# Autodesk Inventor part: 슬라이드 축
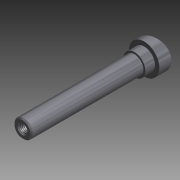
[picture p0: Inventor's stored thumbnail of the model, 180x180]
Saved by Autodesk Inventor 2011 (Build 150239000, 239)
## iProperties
Created: 2012-05
Part Number: 슬라이드 축
Document SubType Name: 모델링
Designer: SeoGD™
Mass: 169.555 g
Surface Area: 67.5855 cm^2
Volume: 21.5719 cm^3
Density: 7.86 g/cm^3
Material: 강, 연강
변환 표준: STEP AP214IS
파일 이름: C:\Users\SeoGD\Desktop\?쒗뿕\異?stp
전처리기: Build: 253, Release: 2010 SP1 - Date: Wed 07/29/2009
전송 단위: 밀리미터
불확실성: 0.01
Author: SeoGD™
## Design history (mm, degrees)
sketch "스케치1"
  geometry: L1 (0, 100)-(7.5, 100); L2 (7.5, 100)-(7.5, 0); L3 (7.5, 0)-(12.5, 0); L4 (12.5, 0)-(12.5, -17); L5 (12.5, -17)-(0, -17); L6 (0, -17)-(0, 100); 1 further point
  constraints: 12 end point, 2 parallel, 2 point on line, 1 perpendicular, 1 vertical
  dimensions: "d0" = 100 distance from line of L1 point (0, 0); "d1" = 15 diameter of L2 L6; "d2" = 25 diameter of L4 L6; "d3" = 17 distance of L3.end L4.end
revolve "회전1" sketch "스케치1" stored, may be unused: angle "d4" = 90 deg
sketch "스케치2"
  geometry: L1 (12.5, 0)-(12.5, -17) reference; L2 (-12.5, -17)-(12.5, -17) reference; L3 (-12.5, 0)-(-12.5, -17) reference; L4 (12.5, -5)-(-12.5, -11.699); L5 (-12.5, 0)-(12.5, 0) reference; 1 further point
  constraints: 2 end point, 2 point on line
  dimensions: "d5" = 75 deg angle of L1 L4; "d6" = 5 distance from line of L4.start L5
extrude "돌출1" cut sketch "스케치2" stored distance "d7" = 10; taper "d8" = 0 deg
chamfer "모따기1" distance "d9" = 1; stored, may be unused: second distance "d10" = 2, angle "d11" = 45 deg
fillet "모깎기1" dims "d12" = 0.5
hole "구멍1" diameter "d15" = 6.647; stored, may be unused: countersink angle "d19" = 90 deg, drill point angle "d21" = 118 deg; dims "d13" = 10, "d14" = 10, "d16" = 17, "d17" = 4, "d18" = 2, "d20" = 20
chamfer "모따기2" distance "d22" = 1; stored, may be unused: second distance "d23" = 2, angle "d24" = 45 deg
sketch "스케치3"
  geometry: C1 r 9 at (0, 0); 1 further point
  constraints: 1 centre point, 1 coincident
  dimensions: "d25" = 18 diameter of C1
extrude "돌출2" join sketch "스케치3" distance "d26" = 8; taper "d27" = 0 deg
node "솔리드1"
node "솔리드 본체"
node "곡면 본체"
node "솔리드2"
